Omron CX-Programmer project 新工程 (CX-Programmer 9.51)

# PLC 新PLC1: CP1H X

## Program 新程序1 (cyclic task 0)

### Section 段1

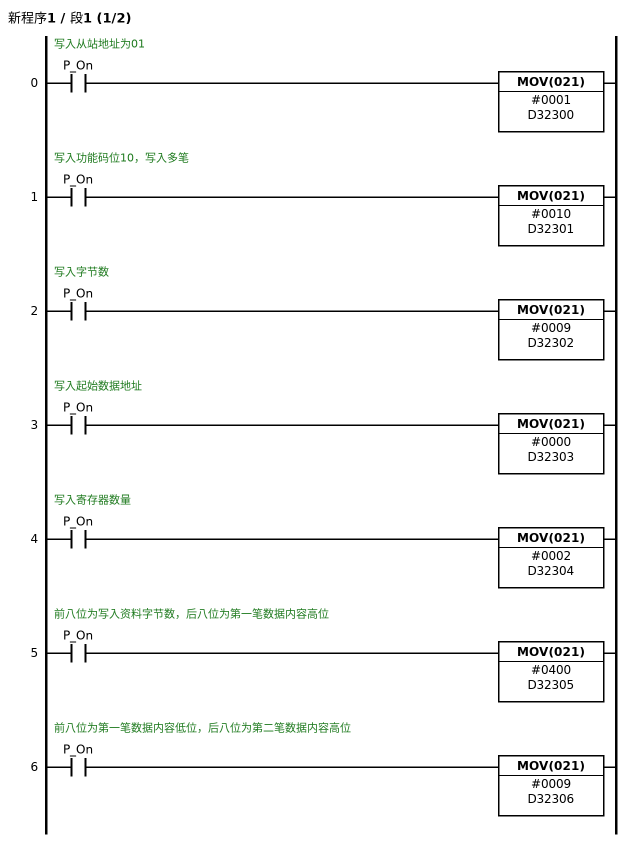
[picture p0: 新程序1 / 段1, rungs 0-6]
; rung 0: 写入从站地址为01
LD P_On
MOV(021) #0001 D32300
; rung 1: 写入功能码位10，写入多笔
LD P_On
MOV(021) #0010 D32301
; rung 2: 写入字节数
LD P_On
MOV(021) #0009 D32302
; rung 3: 写入起始数据地址
LD P_On
MOV(021) #0000 D32303
; rung 4: 写入寄存器数量
LD P_On
MOV(021) #0002 D32304
; rung 5: 前八位为写入资料字节数，后八位为第一笔数据内容高位
LD P_On
MOV(021) #0400 D32305
; rung 6: 前八位为第一笔数据内容低位，后八位为第二笔数据内容高位
LD P_On
MOV(021) #0009 D32306

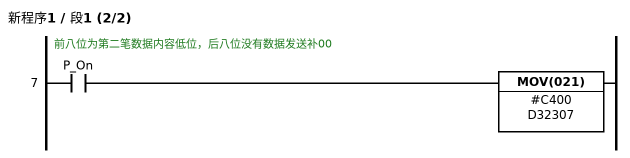
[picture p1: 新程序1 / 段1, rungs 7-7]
; rung 7: 前八位为第二笔数据内容低位，后八位没有数据发送补00
LD P_On
MOV(021) #C400 D32307

### Section END
; rung 0
END(001)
